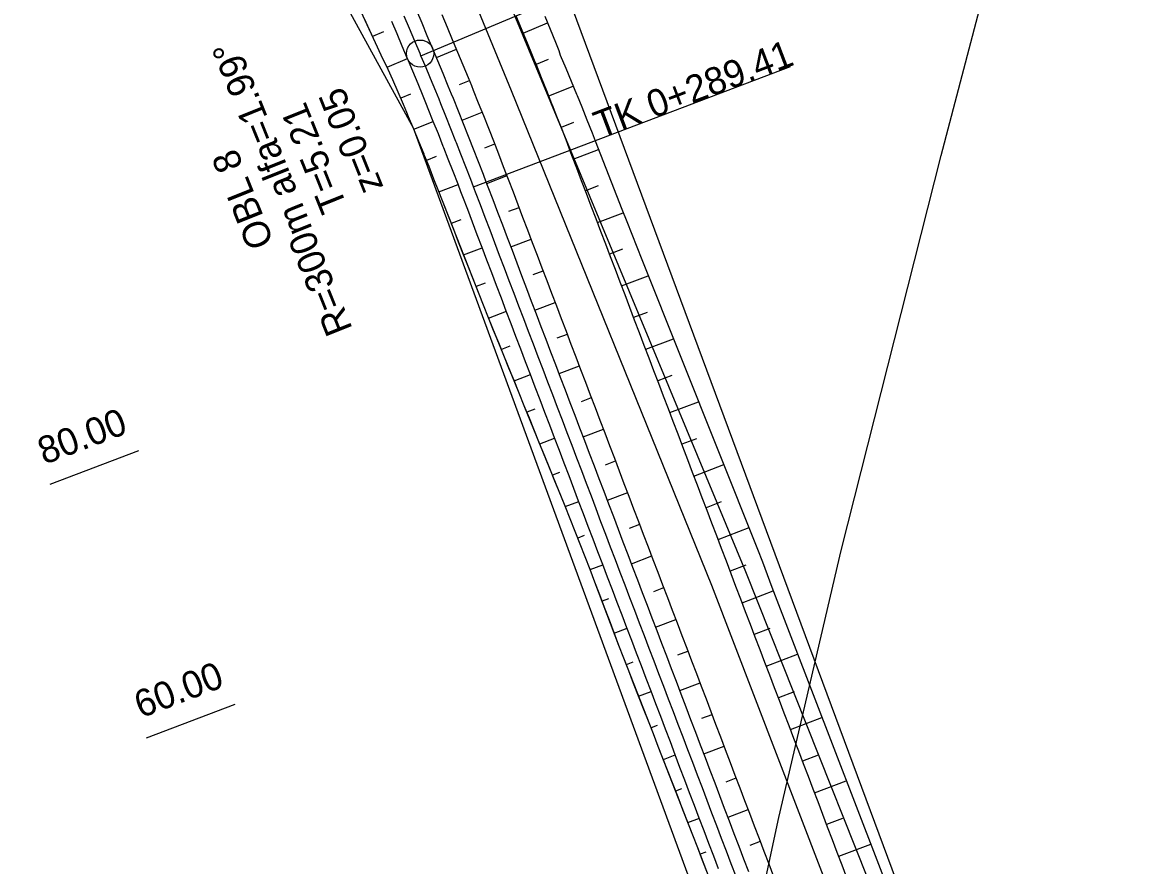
# Model space of a CAD drawing. Extents: x -583721 to -583071, y -1166145 to -1165065.
# Drawn here: x -583477.8 to -583394.9, y -1165419.8 to -1165357.6 of the extents above; entities that cross this region are included whole.
import ezdxf

# ---------------------------------------------------------------- set-up
doc = ezdxf.new("R2010")
doc.units = 0
for name, color, linetype in [('01_DOPRAVA', 7, 'Continuous'), ('03_PC_POPIS_NAVRH', 7, 'Continuous'), ('14', 7, 'Continuous'), ('21', 7, 'Continuous'), ('KOTY', 7, 'Continuous'), ('Popis PP', 7, 'Continuous'), ('TISK', 7, 'Continuous'), ('Trojúhelniky', 7, 'Continuous')]:
    doc.layers.add(name, color=color, linetype=linetype)

msp = doc.modelspace()

# ---------------------------------------------------------------- linework, layer by layer
at = {"layer": '01_DOPRAVA'}
for points in [[(-583394.35, -1165470.85), (-583401.02, -1165469.37), (-583406.34, -1165439.81), (-583441.73, -1165344.5), (-583443.26, -1165334.4), (-583448.82, -1165319.07), (-583454.83, -1165307.19)], [(-583415.62, -1165476.12), (-583415.02, -1165472.65), (-583420.22, -1165443.6), (-583448.97, -1165365.39), (-583458.92, -1165347.2), (-583477.78, -1165313.78)]]:
    msp.add_lwpolyline(points, dxfattribs=at)
at = {"layer": '03_PC_POPIS_NAVRH'}
for points in [[(-583461.59, -1165302.25), (-583452.7, -1165330.11), (-583439.53, -1165361.89), (-583424.49, -1165398.09), (-583411.01, -1165432.01), (-583399.44, -1165466.53), (-583397.85, -1165474.11)], [(-583464.75, -1165303.13), (-583454.71, -1165331.15), (-583441.76, -1165362.61), (-583427, -1165399.08), (-583414.01, -1165432.94), (-583402.68, -1165467.21), (-583401.88, -1165473.68), (-583399.3, -1165487.37), (-583400.15, -1165499.25), (-583403.33, -1165538.26), (-583407.25, -1165561.02), (-583404.58, -1165574.64), (-583401.09, -1165602.76), (-583401.09, -1165613.37), (-583400.94, -1165621.86)]]:
    msp.add_lwpolyline(points, dxfattribs=at)
at = {"layer": '14'}
for p, q in [((-583440.874, -1165358.383), (-583439.086, -1165357.641)), ((-583451.178, -1165358.305), (-583451.98, -1165358.643)), ((-583450.916, -1165360.904), (-583449.406, -1165360.272)), ((-583447.274, -1165360.183), (-583445.798, -1165359.567)), ((-583439.043, -1165360.338), (-583439.924, -1165360.696)), ((-583445.578, -1165362.19), (-583444.838, -1165361.887)), ((-583438.993, -1165363.016), (-583437.194, -1165362.302)), ((-583449.178, -1165362.881), (-583449.91, -1165363.183)), ((-583445.382, -1165364.811), (-583443.896, -1165364.218)), ((-583448.942, -1165365.474), (-583447.503, -1165364.895)), ((-583437.166, -1165364.989), (-583438.081, -1165365.343)), ((-583443.719, -1165366.846), (-583442.974, -1165366.555)), ((-583447.29, -1165367.497), (-583448, -1165367.776)), ((-583437.187, -1165367.678), (-583435.331, -1165366.97)), ((-583443.567, -1165369.469), (-583442.072, -1165368.898)), ((-583447.088, -1165370.092), (-583445.677, -1165369.55)), ((-583435.361, -1165369.658), (-583436.298, -1165370.015)), ((-583441.93, -1165371.522), (-583441.182, -1165371.237)), ((-583435.409, -1165372.351), (-583433.514, -1165371.63)), ((-583445.483, -1165372.151), (-583446.179, -1165372.416)), ((-583445.268, -1165374.744), (-583443.898, -1165374.223)), ((-583441.789, -1165374.143), (-583440.293, -1165373.574)), ((-583433.555, -1165374.321), (-583434.52, -1165374.688)), ((-583440.152, -1165376.195), (-583439.404, -1165375.91)), ((-583443.683, -1165376.816), (-583444.356, -1165377.072)), ((-583433.631, -1165377.024), (-583431.665, -1165376.276)), ((-583440.011, -1165378.816), (-583438.515, -1165378.247)), ((-583443.435, -1165379.396), (-583442.12, -1165378.896)), ((-583431.739, -1165378.979), (-583432.742, -1165379.361)), ((-583438.374, -1165380.868), (-583437.626, -1165380.584)), ((-583431.853, -1165381.698), (-583429.808, -1165380.92)), ((-583441.861, -1165381.472), (-583442.49, -1165381.712)), ((-583438.233, -1165383.489), (-583436.737, -1165382.92)), ((-583441.545, -1165384.027), (-583440.342, -1165383.569)), ((-583429.922, -1165383.638), (-583430.964, -1165384.034)), ((-583436.596, -1165385.541), (-583435.848, -1165385.257)), ((-583430.075, -1165386.371), (-583427.952, -1165385.563)), ((-583440.028, -1165386.125), (-583440.603, -1165386.343)), ((-583436.455, -1165388.162), (-583434.959, -1165387.593)), ((-583439.663, -1165388.66), (-583438.564, -1165388.242)), ((-583428.105, -1165388.296), (-583429.186, -1165388.707)), ((-583434.818, -1165390.214), (-583434.07, -1165389.93)), ((-583438.199, -1165390.778), (-583438.722, -1165390.978)), ((-583428.297, -1165391.044), (-583426.095, -1165390.206)), ((-583434.677, -1165392.835), (-583433.181, -1165392.266)), ((-583437.782, -1165393.295), (-583436.786, -1165392.916)), ((-583426.287, -1165392.954), (-583427.408, -1165393.381)), ((-583433.04, -1165394.888), (-583432.292, -1165394.603)), ((-583426.519, -1165395.717), (-583424.239, -1165394.85)), ((-583436.38, -1165395.436), (-583436.862, -1165395.619)), ((-583432.899, -1165397.509), (-583431.403, -1165396.94)), ((-583435.948, -1165397.947), (-583435.008, -1165397.589)), ((-583424.48, -1165397.616), (-583425.63, -1165398.054)), ((-583431.262, -1165399.561), (-583430.514, -1165399.276)), ((-583424.741, -1165400.39), (-583422.455, -1165399.521)), ((-583434.587, -1165400.103), (-583435.054, -1165400.281)), ((-583431.121, -1165402.182), (-583429.625, -1165401.613)), ((-583434.17, -1165402.62), (-583433.23, -1165402.262)), ((-583422.705, -1165402.29), (-583423.852, -1165402.727)), ((-583429.484, -1165404.234), (-583428.736, -1165403.949)), ((-583422.963, -1165405.064), (-583420.66, -1165404.187)), ((-583432.811, -1165404.777), (-583433.281, -1165404.956)), ((-583429.343, -1165406.855), (-583427.847, -1165406.286)), ((-583432.371, -1165407.285), (-583431.452, -1165406.935)), ((-583420.918, -1165406.96), (-583422.074, -1165407.4)), ((-583427.706, -1165408.907), (-583426.958, -1165408.623)), ((-583421.185, -1165409.737), (-583418.864, -1165408.854)), ((-583431.012, -1165409.443), (-583431.461, -1165409.614)), ((-583430.553, -1165411.943), (-583429.674, -1165411.608)), ((-583427.565, -1165411.528), (-583426.069, -1165410.959)), ((-583419.131, -1165411.63), (-583420.296, -1165412.073)), ((-583425.928, -1165413.58), (-583425.18, -1165413.296)), ((-583429.216, -1165414.109), (-583429.646, -1165414.273)), ((-583419.407, -1165414.41), (-583417.068, -1165413.52)), ((-583425.787, -1165416.201), (-583424.291, -1165415.632)), ((-583428.739, -1165416.602), (-583427.896, -1165416.282)), ((-583417.344, -1165416.3), (-583418.518, -1165416.746)), ((-583424.15, -1165418.254), (-583423.402, -1165417.969)), ((-583417.629, -1165419.083), (-583415.272, -1165418.186)), ((-583427.421, -1165418.776), (-583427.836, -1165418.934))]:
    msp.add_line(p, q, dxfattribs=at)
at = {"layer": '21'}
for points in [[(-583424.815, -1165426.857), (-583428.021, -1165418.448), (-583428.383, -1165417.516), (-583430.923, -1165410.993), (-583431.287, -1165410.061), (-583433.47, -1165404.472), (-583433.824, -1165403.537), (-583435.591, -1165398.86), (-583435.956, -1165397.928), (-583437.418, -1165394.205), (-583437.79, -1165393.276), (-583440.798, -1165385.862), (-583441.175, -1165384.935), (-583443.442, -1165379.378), (-583443.817, -1165378.451), (-583446.881, -1165370.623), (-583447.095, -1165370.074), (-583447.456, -1165369.15), (-583447.82, -1165368.228), (-583448.144, -1165367.417), (-583448.188, -1165367.307), (-583448.562, -1165366.389), (-583448.942, -1165365.473), (-583449.326, -1165364.558), (-583449.463, -1165364.233), (-583449.712, -1165363.645), (-583450.102, -1165362.734), (-583450.495, -1165361.824), (-583450.836, -1165361.073), (-583451.337, -1165360.016), (-583451.764, -1165359.111), (-583453.438, -1165355.475)], [(-583424.256, -1165420.225), (-583424.611, -1165419.29), (-583424.967, -1165418.356), (-583425.322, -1165417.421), (-583425.678, -1165416.487), (-583426.034, -1165415.552), (-583426.389, -1165414.617), (-583426.745, -1165413.683), (-583427.1, -1165412.748), (-583427.456, -1165411.813), (-583427.812, -1165410.879), (-583428.167, -1165409.944), (-583428.523, -1165409.009), (-583428.878, -1165408.075), (-583429.234, -1165407.14), (-583429.59, -1165406.206), (-583429.945, -1165405.271), (-583430.301, -1165404.336), (-583430.656, -1165403.402), (-583431.012, -1165402.467), (-583431.368, -1165401.532), (-583431.723, -1165400.598), (-583432.079, -1165399.663), (-583432.434, -1165398.728), (-583432.79, -1165397.794), (-583433.146, -1165396.859), (-583433.501, -1165395.925), (-583433.857, -1165394.99), (-583434.212, -1165394.055), (-583434.568, -1165393.121), (-583434.924, -1165392.186), (-583435.279, -1165391.251), (-583435.635, -1165390.317), (-583435.99, -1165389.382), (-583436.346, -1165388.447), (-583436.702, -1165387.513), (-583437.057, -1165386.578), (-583437.413, -1165385.644), (-583437.769, -1165384.709), (-583438.124, -1165383.774), (-583438.48, -1165382.84), (-583438.835, -1165381.905), (-583439.191, -1165380.97), (-583439.547, -1165380.036), (-583439.902, -1165379.101), (-583440.258, -1165378.166), (-583440.613, -1165377.232), (-583440.969, -1165376.297), (-583441.325, -1165375.363), (-583441.68, -1165374.428), (-583442.036, -1165373.493), (-583442.391, -1165372.559), (-583442.747, -1165371.624), (-583443.103, -1165370.689), (-583443.458, -1165369.755), (-583443.602, -1165369.376), (-583443.815, -1165368.818), (-583444.175, -1165367.882), (-583444.539, -1165366.947), (-583444.861, -1165366.124), (-583444.905, -1165366.013), (-583445.275, -1165365.08), (-583445.647, -1165364.148), (-583446.023, -1165363.218), (-583446.157, -1165362.887), (-583446.402, -1165362.289), (-583446.784, -1165361.361), (-583447.169, -1165360.435), (-583447.491, -1165359.666), (-583447.557, -1165359.51), (-583447.945, -1165358.588), (-583448.332, -1165357.667), (-583448.72, -1165356.745)], [(-583427.308, -1165420.317), (-583427.665, -1165419.382), (-583428.021, -1165418.448), (-583428.383, -1165417.516), (-583428.746, -1165416.584), (-583429.109, -1165415.652), (-583429.472, -1165414.72), (-583429.835, -1165413.788), (-583430.198, -1165412.856), (-583430.561, -1165411.925), (-583430.923, -1165410.993), (-583431.287, -1165410.061), (-583431.651, -1165409.13), (-583432.014, -1165408.198), (-583432.378, -1165407.266), (-583432.742, -1165406.335), (-583433.106, -1165405.403), (-583433.47, -1165404.472), (-583433.824, -1165403.537), (-583434.177, -1165402.601), (-583434.531, -1165401.666), (-583434.884, -1165400.73), (-583435.238, -1165399.795), (-583435.591, -1165398.86), (-583435.956, -1165397.928), (-583436.321, -1165396.997), (-583436.687, -1165396.066), (-583437.052, -1165395.136), (-583437.418, -1165394.205), (-583437.79, -1165393.276), (-583438.166, -1165392.35), (-583438.542, -1165391.423), (-583438.918, -1165390.496), (-583439.294, -1165389.569), (-583439.67, -1165388.642), (-583440.046, -1165387.715), (-583440.422, -1165386.788), (-583440.798, -1165385.862), (-583441.175, -1165384.935), (-583441.553, -1165384.009), (-583441.931, -1165383.083), (-583442.309, -1165382.157), (-583442.686, -1165381.23), (-583443.064, -1165380.304), (-583443.442, -1165379.378), (-583443.817, -1165378.451), (-583444.181, -1165377.519), (-583444.546, -1165376.588), (-583444.91, -1165375.657), (-583445.275, -1165374.726), (-583445.64, -1165373.794), (-583446.004, -1165372.863), (-583446.369, -1165371.932), (-583446.733, -1165371.001), (-583446.881, -1165370.623), (-583447.095, -1165370.074), (-583447.456, -1165369.15), (-583447.82, -1165368.228), (-583448.144, -1165367.417), (-583448.188, -1165367.307), (-583448.562, -1165366.389), (-583448.942, -1165365.473), (-583449.326, -1165364.558), (-583449.463, -1165364.233), (-583449.712, -1165363.645), (-583450.102, -1165362.734), (-583450.495, -1165361.824), (-583450.836, -1165361.073), (-583450.908, -1165360.92), (-583451.337, -1165360.016), (-583451.764, -1165359.111), (-583452.183, -1165358.202), (-583452.601, -1165357.293)], [(-583426.48, -1165420.002), (-583426.836, -1165419.067), (-583427.192, -1165418.132), (-583427.547, -1165417.198), (-583427.903, -1165416.263), (-583428.259, -1165415.328), (-583428.614, -1165414.394), (-583428.97, -1165413.459), (-583429.325, -1165412.525), (-583429.681, -1165411.59), (-583430.037, -1165410.655), (-583430.392, -1165409.721), (-583430.748, -1165408.786), (-583431.103, -1165407.851), (-583431.459, -1165406.917), (-583431.815, -1165405.982), (-583432.17, -1165405.047), (-583432.526, -1165404.113), (-583432.881, -1165403.178), (-583433.237, -1165402.244), (-583433.593, -1165401.309), (-583433.948, -1165400.374), (-583434.304, -1165399.44), (-583434.659, -1165398.505), (-583435.015, -1165397.57), (-583435.371, -1165396.636), (-583435.726, -1165395.701), (-583436.082, -1165394.766), (-583436.437, -1165393.832), (-583436.793, -1165392.897), (-583437.149, -1165391.963), (-583437.504, -1165391.028), (-583437.86, -1165390.093), (-583438.215, -1165389.159), (-583438.571, -1165388.224), (-583438.927, -1165387.289), (-583439.282, -1165386.355), (-583439.638, -1165385.42), (-583439.993, -1165384.485), (-583440.349, -1165383.551), (-583440.705, -1165382.616), (-583441.06, -1165381.682), (-583441.416, -1165380.747), (-583441.771, -1165379.812), (-583442.127, -1165378.878), (-583442.483, -1165377.943), (-583442.838, -1165377.008), (-583443.194, -1165376.074), (-583443.549, -1165375.139), (-583443.905, -1165374.204), (-583444.261, -1165373.27), (-583444.616, -1165372.335), (-583444.972, -1165371.401), (-583445.327, -1165370.466), (-583445.472, -1165370.087), (-583445.683, -1165369.533), (-583446.041, -1165368.603), (-583446.402, -1165367.674), (-583446.722, -1165366.857), (-583446.766, -1165366.746), (-583447.133, -1165365.82), (-583447.503, -1165364.894), (-583447.876, -1165363.97), (-583448.01, -1165363.642), (-583448.252, -1165363.047), (-583448.632, -1165362.126), (-583449.014, -1165361.205), (-583449.335, -1165360.442), (-583449.4, -1165360.286), (-583449.788, -1165359.364), (-583450.176, -1165358.442), (-583450.564, -1165357.521)], [(-583422.405, -1165420.591), (-583422.76, -1165419.656), (-583423.116, -1165418.722), (-583423.471, -1165417.787), (-583423.827, -1165416.852), (-583424.183, -1165415.918), (-583424.538, -1165414.983), (-583424.894, -1165414.048), (-583425.249, -1165413.114), (-583425.605, -1165412.179), (-583425.961, -1165411.244), (-583426.316, -1165410.31), (-583426.672, -1165409.375), (-583427.027, -1165408.441), (-583427.383, -1165407.506), (-583427.739, -1165406.571), (-583428.094, -1165405.637), (-583428.45, -1165404.702), (-583428.805, -1165403.767), (-583429.161, -1165402.833), (-583429.517, -1165401.898), (-583429.872, -1165400.963), (-583430.228, -1165400.029), (-583430.583, -1165399.094), (-583430.939, -1165398.159), (-583431.295, -1165397.225), (-583431.65, -1165396.29), (-583432.006, -1165395.356), (-583432.361, -1165394.421), (-583432.717, -1165393.486), (-583433.073, -1165392.552), (-583433.428, -1165391.617), (-583433.784, -1165390.682), (-583434.139, -1165389.748), (-583434.495, -1165388.813), (-583434.851, -1165387.878), (-583435.206, -1165386.944), (-583435.562, -1165386.009), (-583435.917, -1165385.075), (-583436.273, -1165384.14), (-583436.629, -1165383.205), (-583436.984, -1165382.271), (-583437.34, -1165381.336), (-583437.696, -1165380.401), (-583438.051, -1165379.467), (-583438.407, -1165378.532), (-583438.762, -1165377.597), (-583439.118, -1165376.663), (-583439.474, -1165375.728), (-583439.829, -1165374.794), (-583440.185, -1165373.859), (-583440.54, -1165372.924), (-583440.896, -1165371.99), (-583441.252, -1165371.055), (-583441.607, -1165370.12), (-583441.963, -1165369.186), (-583442.107, -1165368.807), (-583442.321, -1165368.246), (-583442.683, -1165367.305), (-583443.048, -1165366.365), (-583443.372, -1165365.538), (-583443.416, -1165365.426), (-583443.788, -1165364.488), (-583444.163, -1165363.552), (-583444.54, -1165362.616), (-583444.676, -1165362.284), (-583444.921, -1165361.682), (-583445.305, -1165360.75), (-583445.692, -1165359.818), (-583446.016, -1165359.045), (-583446.082, -1165358.889), (-583446.47, -1165357.968), (-583446.858, -1165357.046)], [(-583417.02, -1165420.682), (-583417.376, -1165419.747), (-583417.731, -1165418.813), (-583418.087, -1165417.878), (-583418.443, -1165416.943), (-583418.798, -1165416.009), (-583419.154, -1165415.074), (-583419.509, -1165414.14), (-583419.865, -1165413.205), (-583420.221, -1165412.27), (-583420.576, -1165411.336), (-583420.932, -1165410.401), (-583421.287, -1165409.466), (-583421.643, -1165408.532), (-583421.999, -1165407.597), (-583422.354, -1165406.662), (-583422.71, -1165405.728), (-583423.065, -1165404.793), (-583423.421, -1165403.859), (-583423.777, -1165402.924), (-583424.132, -1165401.989), (-583424.488, -1165401.055), (-583424.843, -1165400.12), (-583425.199, -1165399.185), (-583425.555, -1165398.251), (-583425.91, -1165397.316), (-583426.266, -1165396.381), (-583426.621, -1165395.447), (-583426.977, -1165394.512), (-583427.333, -1165393.578), (-583427.688, -1165392.643), (-583428.044, -1165391.708), (-583428.399, -1165390.774), (-583428.755, -1165389.839), (-583429.111, -1165388.904), (-583429.466, -1165387.97), (-583429.822, -1165387.035), (-583430.177, -1165386.1), (-583430.533, -1165385.166), (-583430.889, -1165384.231), (-583431.244, -1165383.297), (-583431.6, -1165382.362), (-583431.956, -1165381.427), (-583432.311, -1165380.493), (-583432.667, -1165379.558), (-583433.022, -1165378.623), (-583433.378, -1165377.689), (-583433.734, -1165376.754), (-583434.089, -1165375.819), (-583434.445, -1165374.885), (-583434.8, -1165373.95), (-583435.156, -1165373.016), (-583435.512, -1165372.081), (-583435.867, -1165371.146), (-583436.223, -1165370.212), (-583436.578, -1165369.277), (-583436.934, -1165368.342), (-583437.29, -1165367.408), (-583437.434, -1165367.029), (-583437.651, -1165366.459), (-583438.019, -1165365.502), (-583438.39, -1165364.547), (-583438.72, -1165363.706), (-583438.765, -1165363.592), (-583439.143, -1165362.639), (-583439.523, -1165361.687), (-583439.907, -1165360.736), (-583440.045, -1165360.398), (-583440.295, -1165359.787), (-583440.685, -1165358.839), (-583441.078, -1165357.892), (-583441.408, -1165357.106)], [(-583439.297, -1165357.148), (-583438.892, -1165358.097), (-583438.49, -1165359.047), (-583438.242, -1165359.664), (-583438.152, -1165360.023), (-583437.743, -1165360.971), (-583437.349, -1165361.925), (-583436.958, -1165362.88), (-583436.912, -1165362.994), (-583436.571, -1165363.836), (-583436.187, -1165364.794), (-583435.807, -1165365.753), (-583435.582, -1165366.324), (-583433.621, -1165371.362), (-583433.25, -1165372.29), (-583432.881, -1165373.22), (-583432.514, -1165374.15), (-583432.143, -1165375.079), (-583423.604, -1165396.438), (-583423.257, -1165397.377), (-583422.909, -1165398.314), (-583422.559, -1165399.251), (-583411.784, -1165427.249)]]:
    msp.add_lwpolyline(points, dxfattribs=at)
at = {"layer": 'KOTY'}
msp.add_lwpolyline([(-583425.19, -1165420.581), (-583425.546, -1165419.646), (-583425.901, -1165418.711), (-583426.257, -1165417.777), (-583426.613, -1165416.842), (-583426.968, -1165415.908), (-583427.324, -1165414.973), (-583427.679, -1165414.038), (-583428.035, -1165413.104), (-583428.391, -1165412.169), (-583428.746, -1165411.234), (-583429.102, -1165410.3), (-583429.457, -1165409.365), (-583429.813, -1165408.43), (-583430.169, -1165407.496), (-583430.524, -1165406.561), (-583430.88, -1165405.627), (-583431.235, -1165404.692), (-583431.591, -1165403.757), (-583431.947, -1165402.823), (-583432.302, -1165401.888), (-583432.658, -1165400.953), (-583433.014, -1165400.019), (-583433.369, -1165399.084), (-583433.725, -1165398.149), (-583434.08, -1165397.215), (-583434.436, -1165396.28), (-583434.792, -1165395.346), (-583435.147, -1165394.411), (-583435.503, -1165393.476), (-583435.858, -1165392.542), (-583436.214, -1165391.607), (-583436.57, -1165390.672), (-583436.925, -1165389.738), (-583437.281, -1165388.803), (-583437.636, -1165387.868), (-583437.992, -1165386.934), (-583438.348, -1165385.999), (-583438.703, -1165385.065), (-583439.059, -1165384.13), (-583439.414, -1165383.195), (-583439.77, -1165382.261), (-583440.126, -1165381.326), (-583440.481, -1165380.391), (-583440.837, -1165379.457), (-583441.192, -1165378.522), (-583441.548, -1165377.587), (-583441.904, -1165376.653), (-583442.259, -1165375.718), (-583442.615, -1165374.783), (-583442.97, -1165373.849), (-583443.326, -1165372.914), (-583443.682, -1165371.98), (-583444.037, -1165371.045), (-583444.393, -1165370.11), (-583444.537, -1165369.731), (-583444.749, -1165369.176), (-583445.108, -1165368.243), (-583445.47, -1165367.31), (-583445.792, -1165366.491), (-583445.835, -1165366.379), (-583446.204, -1165365.45), (-583446.575, -1165364.521), (-583446.95, -1165363.594), (-583447.084, -1165363.265), (-583447.327, -1165362.668), (-583447.708, -1165361.743), (-583448.092, -1165360.82), (-583448.413, -1165360.054), (-583448.478, -1165359.898), (-583448.866, -1165358.976), (-583449.254, -1165358.054), (-583449.642, -1165357.133)], dxfattribs=at)
at = {"layer": 'Popis PP'}
msp.add_lwpolyline([(-583453.882, -1165797.966), (-583451.761, -1165745.072), (-583447.631, -1165643.262), (-583446.859, -1165623.987), (-583445.813, -1165599.542), (-583444.662, -1165577.371), (-583442.034, -1165542.78), (-583439.667, -1165520.038), (-583436.68, -1165496.549), (-583431.494, -1165463.535), (-583426.631, -1165437.638), (-583422.051, -1165416.223), (-583417.441, -1165396.545), (-583410.087, -1165367.405), (-583389.989, -1165290.805), (-583376.799, -1165240.446), (-583367.037, -1165203.237), (-583351.367, -1165143.48), (-583345.203, -1165119.977)], dxfattribs=at)
at = {"layer": 'TISK'}
for points in [[(-583448.413, -1165360.054), (-583425.37, -1165350.357)], [(-583444.537, -1165369.731), (-583421.171, -1165360.841)]]:
    msp.add_lwpolyline(points, dxfattribs=at)
at = {"layer": 'Trojúhelniky'}
for p, q in [((-583469.231, -1165389.19), (-583475.774, -1165391.679)), ((-583462.119, -1165407.883), (-583468.662, -1165410.372))]:
    msp.add_line(p, q, dxfattribs=at)
msp.add_circle((-583448.478, -1165359.898), 1, dxfattribs=at)

# ---------------------------------------------------------------- texts
at = {"layer": 'TISK'}
for s, rotation, p in [('R=300m alfa=1.99%%d', 111.82592, (-583453.436, -1165380.197)), ('TK 0+289.41', 20.83038, (-583435.191, -1165366.175)), ('   z=0.05', 111.82592, (-583450.328, -1165371.819)), ('  T=5.21', 111.82592, (-583453.273, -1165372.535)), ('OBL 8', 111.82592, (-583459.219, -1165373.827)), ('80.00', 20.83038, (-583476.172, -1165390.226)), ('60.00', 20.83038, (-583469.06, -1165408.919))]:
    msp.add_text(s, height=2, rotation=rotation, dxfattribs=at).set_placement(p)

doc.saveas('drawing.dxf')
